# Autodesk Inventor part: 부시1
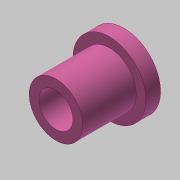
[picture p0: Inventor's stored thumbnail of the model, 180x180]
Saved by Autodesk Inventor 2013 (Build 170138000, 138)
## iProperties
Created: 2020-03
Part Number: 부시1
Material: 스테인리스강
Document SubType Name: Modeling
Designer: mduedu
Density: 1 g/cm^3
Author: mduedu
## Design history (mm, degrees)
sketch "스케치1"
  geometry: L1 (0, 0)-(11, 0); L2 (11, 0)-(11, 5.5); L3 (11, 5.5)-(0, 5.5); L4 (0, 5.5)-(0, 0); L5 (11, 0)-(14, 0); L6 (14, 0)-(14, 7.5); L7 (14, 7.5)-(11, 7.5); L8 (11, 7.5)-(11, 0)
  constraints: 16 end point, 4 parallel, 2 horizontal, 2 perpendicular
  dimensions: "d0" = 14 distance between parallel lines of L6 L4; "d2" = 11 diameter of L3 L1; "d3" = 15 diameter of L7 L5; "d4" = 3 distance of L6.end L7.end
revolve "회전1" sketch "스케치1" stored, may be unused: angle "d5" = 90 deg
hole "구멍1" diameter "d8" = 7; stored, may be unused: countersink angle "d12" = 90 deg, drill point angle "d14" = 118 deg; dims "d6" = 10, "d7" = 10, "d9" = 6, "d10" = 4, "d11" = 2, "d13" = 8
node "솔리드1"
